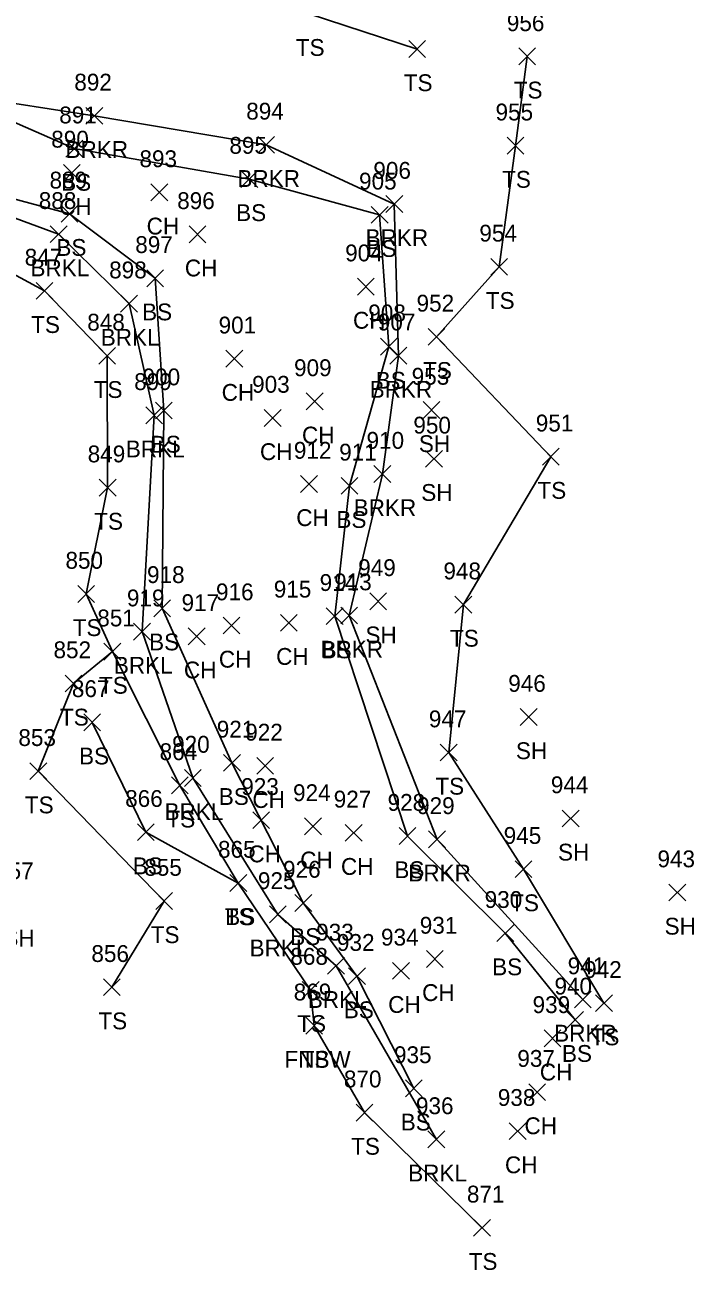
# Model space of a CAD drawing. Extents: x 1638705 to 1644019, y 630225 to 637423.
# Drawn here: x 1643939.5 to 1644019, y 636918.9 to 637066.8 of the extents above; entities that cross this region are included whole.
import ezdxf

# ---------------------------------------------------------------- set-up
doc = ezdxf.new("R2010")
doc.units = 0
for name, color, linetype in [('L_A', 7, 'Continuous'), ('L_I', 7, 'Continuous'), ('L_TIC', 7, 'Continuous'), ('LAWE', 7, 'Continuous'), ('LELB', 7, 'Continuous')]:
    doc.layers.add(name, color=color, linetype=linetype)

msp = doc.modelspace()

# ---------------------------------------------------------------- linework, layer by layer
at = {"layer": 'L_TIC'}
for points in [[(1643985.07, 637062.95), (1643987.07, 637064.95)], [(1643987.07, 637062.95), (1643985.07, 637064.95)], [(1643998.13, 637062.08), (1644000.13, 637064.08)], [(1644000.13, 637062.08), (1643998.13, 637064.08)], [(1643946.72, 637055.02), (1643948.72, 637057.02)], [(1643948.72, 637055.02), (1643946.72, 637057.02)], [(1643967.13, 637051.57), (1643969.13, 637053.57)], [(1643969.13, 637051.57), (1643967.13, 637053.57)], [(1643996.75, 637051.47), (1643998.75, 637053.47)], [(1643998.75, 637051.47), (1643996.75, 637053.47)], [(1643944.35, 637051.12), (1643946.35, 637053.12)], [(1643946.35, 637051.12), (1643944.35, 637053.12)], [(1643944.06, 637048.24), (1643946.06, 637050.24)], [(1643946.06, 637048.24), (1643944.06, 637050.24)], [(1643965.13, 637047.51), (1643967.13, 637049.51)], [(1643967.13, 637047.51), (1643965.13, 637049.51)], [(1643954.45, 637045.92), (1643956.45, 637047.92)], [(1643956.45, 637045.92), (1643954.45, 637047.92)], [(1643982.36, 637044.54), (1643984.36, 637046.54)], [(1643984.36, 637044.54), (1643982.36, 637046.54)], [(1643943.78, 637043.38), (1643945.78, 637045.38)], [(1643945.78, 637043.38), (1643943.78, 637045.38)], [(1643980.61, 637043.26), (1643982.61, 637045.26)], [(1643982.61, 637043.26), (1643980.61, 637045.26)], [(1643942.49, 637040.95), (1643944.49, 637042.95)], [(1643944.49, 637040.95), (1643942.49, 637042.95)], [(1643958.99, 637040.94), (1643960.99, 637042.94)], [(1643960.99, 637040.94), (1643958.99, 637042.94)], [(1643994.82, 637037.08), (1643996.82, 637039.08)], [(1643996.82, 637037.08), (1643994.82, 637039.08)], [(1643953.95, 637035.72), (1643955.95, 637037.72)], [(1643955.95, 637035.72), (1643953.95, 637037.72)], [(1643940.82, 637034.22), (1643942.82, 637036.22)], [(1643942.82, 637034.22), (1643940.82, 637036.22)], [(1643978.97, 637034.73), (1643980.97, 637036.73)], [(1643980.97, 637034.73), (1643978.97, 637036.73)], [(1643950.85, 637032.71), (1643952.85, 637034.71)], [(1643952.85, 637032.71), (1643950.85, 637034.71)], [(1643987.37, 637028.76), (1643989.37, 637030.76)], [(1643989.37, 637028.76), (1643987.37, 637030.76)], [(1643948.25, 637026.5), (1643950.25, 637028.5)], [(1643950.25, 637026.5), (1643948.25, 637028.5)], [(1643963.36, 637026.16), (1643965.36, 637028.16)], [(1643965.36, 637026.16), (1643963.36, 637028.16)], [(1643981.71, 637027.6), (1643983.71, 637029.6)], [(1643983.71, 637027.6), (1643981.71, 637029.6)], [(1643982.84, 637026.52), (1643984.84, 637028.52)], [(1643984.84, 637026.52), (1643982.84, 637028.52)], [(1643972.9, 637021.09), (1643974.9, 637023.09)], [(1643974.9, 637021.09), (1643972.9, 637023.09)], [(1643953.83, 637019.44), (1643955.83, 637021.44)], [(1643955.83, 637019.44), (1643953.83, 637021.44)], [(1643954.99, 637020), (1643956.99, 637022)], [(1643956.99, 637020), (1643954.99, 637022)], [(1643967.91, 637019.12), (1643969.91, 637021.12)], [(1643969.91, 637019.12), (1643967.91, 637021.12)], [(1643986.78, 637020.07), (1643988.78, 637022.07)], [(1643988.78, 637020.07), (1643986.78, 637022.07)], [(1644000.95, 637014.52), (1644002.95, 637016.52)], [(1644002.95, 637014.52), (1644000.95, 637016.52)], [(1643987.07, 637014.27), (1643989.07, 637016.27)], [(1643989.07, 637014.27), (1643987.07, 637016.27)], [(1643980.94, 637012.46), (1643982.94, 637014.46)], [(1643982.94, 637012.46), (1643980.94, 637014.46)], [(1643948.31, 637010.85), (1643950.31, 637012.85)], [(1643950.31, 637010.85), (1643948.31, 637012.85)], [(1643972.22, 637011.28), (1643974.22, 637013.28)], [(1643974.22, 637011.28), (1643972.22, 637013.28)], [(1643977.04, 637011.06), (1643979.04, 637013.06)], [(1643979.04, 637011.06), (1643977.04, 637013.06)], [(1643945.75, 636998.21), (1643947.75, 637000.21)], [(1643947.75, 636998.21), (1643945.75, 637000.21)], [(1643980.44, 636997.34), (1643982.44, 636999.34)], [(1643982.44, 636997.34), (1643980.44, 636999.34)], [(1643990.56, 636996.95), (1643992.56, 636998.95)], [(1643992.56, 636996.95), (1643990.56, 636998.95)], [(1643954.79, 636996.51), (1643956.79, 636998.51)], [(1643956.79, 636996.51), (1643954.79, 636998.51)], [(1643975.28, 636995.57), (1643977.28, 636997.57)], [(1643977.28, 636995.57), (1643975.28, 636997.57)], [(1643977, 636995.65), (1643979, 636997.65)], [(1643979, 636995.65), (1643977, 636997.65)], [(1643952.4, 636993.74), (1643954.4, 636995.74)], [(1643954.4, 636993.74), (1643952.4, 636995.74)], [(1643963.03, 636994.46), (1643965.03, 636996.46)], [(1643965.03, 636994.46), (1643963.03, 636996.46)], [(1643969.83, 636994.79), (1643971.83, 636996.79)], [(1643971.83, 636994.79), (1643969.83, 636996.79)], [(1643958.88, 636993.18), (1643960.88, 636995.18)], [(1643960.88, 636993.18), (1643958.88, 636995.18)], [(1643948.87, 636991.36), (1643950.87, 636993.36)], [(1643950.87, 636991.36), (1643948.87, 636993.36)], [(1643948.87, 636991.36), (1643950.87, 636993.36)], [(1643950.87, 636991.36), (1643948.87, 636993.36)], [(1643944.25, 636987.58), (1643946.25, 636989.58)], [(1643946.25, 636987.58), (1643944.25, 636989.58)], [(1643998.31, 636983.59), (1644000.31, 636985.59)], [(1644000.31, 636983.59), (1643998.31, 636985.59)], [(1643946.47, 636982.96), (1643948.47, 636984.96)], [(1643948.47, 636982.96), (1643946.47, 636984.96)], [(1643988.82, 636979.37), (1643990.82, 636981.37)], [(1643990.82, 636979.37), (1643988.82, 636981.37)], [(1643963.07, 636978.15), (1643965.07, 636980.15)], [(1643965.07, 636978.15), (1643963.07, 636980.15)], [(1643967.01, 636977.79), (1643969.01, 636979.79)], [(1643969.01, 636977.79), (1643967.01, 636979.79)], [(1643940.07, 636977.15), (1643942.07, 636979.15)], [(1643942.07, 636977.15), (1643940.07, 636979.15)], [(1643958.42, 636976.35), (1643960.42, 636978.35)], [(1643960.42, 636976.35), (1643958.42, 636978.35)], [(1643956.89, 636975.47), (1643958.89, 636977.47)], [(1643958.89, 636975.47), (1643956.89, 636977.47)], [(1644003.31, 636971.54), (1644005.31, 636973.54)], [(1644005.31, 636971.54), (1644003.31, 636973.54)], [(1643966.54, 636971.33), (1643968.54, 636973.33)], [(1643968.54, 636971.33), (1643966.54, 636973.33)], [(1643972.69, 636970.6), (1643974.69, 636972.6)], [(1643974.69, 636970.6), (1643972.69, 636972.6)], [(1643952.85, 636969.91), (1643954.85, 636971.91)], [(1643954.85, 636969.91), (1643952.85, 636971.91)], [(1643977.53, 636969.84), (1643979.53, 636971.84)], [(1643979.53, 636969.84), (1643977.53, 636971.84)], [(1643983.92, 636969.45), (1643985.92, 636971.45)], [(1643985.92, 636969.45), (1643983.92, 636971.45)], [(1643987.43, 636969.06), (1643989.43, 636971.06)], [(1643989.43, 636969.06), (1643987.43, 636971.06)], [(1643997.71, 636965.52), (1643999.71, 636967.52)], [(1643999.71, 636965.52), (1643997.71, 636967.52)], [(1643963.83, 636963.87), (1643965.83, 636965.87)], [(1643965.83, 636963.87), (1643963.83, 636965.87)], [(1643963.83, 636963.87), (1643965.83, 636965.87)], [(1643965.83, 636963.87), (1643963.83, 636965.87)], [(1644015.98, 636962.74), (1644017.98, 636964.74)], [(1644017.98, 636962.74), (1644015.98, 636964.74)], [(1643955.03, 636961.73), (1643957.03, 636963.73)], [(1643957.03, 636961.73), (1643955.03, 636963.73)], [(1643971.55, 636961.5), (1643973.55, 636963.5)], [(1643973.55, 636961.5), (1643971.55, 636963.5)], [(1643968.52, 636960.15), (1643970.52, 636962.15)], [(1643970.52, 636960.15), (1643968.52, 636962.15)], [(1643995.54, 636957.91), (1643997.54, 636959.91)], [(1643997.54, 636957.91), (1643995.54, 636959.91)], [(1643975.44, 636954.03), (1643977.44, 636956.03)], [(1643977.44, 636954.03), (1643975.44, 636956.03)], [(1643987.17, 636954.85), (1643989.17, 636956.85)], [(1643989.17, 636954.85), (1643987.17, 636956.85)], [(1643977.92, 636952.81), (1643979.92, 636954.81)], [(1643979.92, 636952.81), (1643977.92, 636954.81)], [(1643983.15, 636953.44), (1643985.15, 636955.44)], [(1643985.15, 636953.44), (1643983.15, 636955.44)], [(1643948.8, 636951.49), (1643950.8, 636953.49)], [(1643950.8, 636951.49), (1643948.8, 636953.49)], [(1643972.42, 636951.16), (1643974.42, 636953.16)], [(1643974.42, 636951.16), (1643972.42, 636953.16)], [(1644004.75, 636950.03), (1644006.75, 636952.03)], [(1644006.75, 636950.03), (1644004.75, 636952.03)], [(1644007.26, 636949.59), (1644009.26, 636951.59)], [(1644009.26, 636949.59), (1644007.26, 636951.59)], [(1643972.83, 636946.92), (1643974.83, 636948.92)], [(1643974.83, 636946.92), (1643972.83, 636948.92)], [(1643972.83, 636946.92), (1643974.83, 636948.92)], [(1643974.83, 636946.92), (1643972.83, 636948.92)], [(1644003.83, 636947.62), (1644005.83, 636949.62)], [(1644005.83, 636947.62), (1644003.83, 636949.62)], [(1644001.15, 636945.42), (1644003.15, 636947.42)], [(1644003.15, 636945.42), (1644001.15, 636947.42)], [(1643984.68, 636939.47), (1643986.68, 636941.47)], [(1643986.68, 636939.47), (1643984.68, 636941.47)], [(1643999.33, 636939.03), (1644001.33, 636941.03)], [(1644001.33, 636939.03), (1643999.33, 636941.03)], [(1643978.82, 636936.59), (1643980.82, 636938.59)], [(1643980.82, 636936.59), (1643978.82, 636938.59)], [(1643987.35, 636933.41), (1643989.35, 636935.41)], [(1643989.35, 636933.41), (1643987.35, 636935.41)], [(1643997.01, 636934.39), (1643999.01, 636936.39)], [(1643999.01, 636934.39), (1643997.01, 636936.39)], [(1643992.78, 636922.91), (1643994.78, 636924.91)], [(1643994.78, 636922.91), (1643992.78, 636924.91)]]:
    msp.add_lwpolyline(points, dxfattribs=at)
at = {"layer": 'LAWE'}
for points in [[(1643920.85, 637053.85), (1643924.81, 637055.54), (1643932.9, 637058.3), (1643947.72, 637056.02), (1643968.13, 637052.57), (1643983.36, 637045.54), (1643983.84, 637027.52), (1643981.94, 637013.46), (1643978, 636996.65), (1643988.43, 636970.06), (1644005.75, 636951.03)], [(1643919.29, 637049.79), (1643922.02, 637046.26), (1643932.4, 637046.02), (1643943.49, 637041.95), (1643951.85, 637033.71), (1643954.83, 637020.44), (1643953.4, 636994.74), (1643959.42, 636977.35), (1643969.52, 636961.15), (1643976.44, 636955.03), (1643988.35, 636934.41)]]:
    msp.add_lwpolyline(points, dxfattribs=at)
at = {"layer": 'LELB'}
for points in [[(1643913.32, 637074.89), (1643919.98, 637075.96), (1643928.62, 637076.78), (1643934.09, 637075.7), (1643944.5, 637076.33), (1643955.28, 637072.94), (1643973.25, 637068.14), (1643986.07, 637063.95)], [(1644008.26, 636950.59), (1643998.71, 636966.52), (1643989.82, 636980.37), (1643991.56, 636997.95), (1644001.95, 637015.52), (1643988.37, 637029.76), (1643995.82, 637038.08), (1643997.75, 637052.47), (1643999.13, 637063.08)], [(1643919.9, 637050.36), (1643921.47, 637053.52), (1643925.5, 637055.06), (1643935.65, 637056.38), (1643945.35, 637052.12), (1643966.13, 637048.51), (1643981.61, 637044.26), (1643982.71, 637028.6), (1643978.04, 637012.06), (1643976.28, 636996.57), (1643984.92, 636970.45), (1643996.54, 636958.91), (1644004.83, 636948.62)], [(1643919.9, 637050.36), (1643922.64, 637048.27), (1643928.54, 637048.75), (1643944.78, 637044.38), (1643954.95, 637036.72), (1643955.99, 637021), (1643955.79, 636997.51), (1643964.07, 636979.15), (1643972.55, 636962.5), (1643978.92, 636953.81), (1643985.68, 636940.47)], [(1643908.72, 636993.2), (1643912.06, 637008.12), (1643918.34, 637027.28), (1643925.98, 637038.19), (1643927.97, 637042.71), (1643941.82, 637035.22), (1643949.25, 637027.5), (1643949.31, 637011.85), (1643946.75, 636999.21), (1643949.87, 636992.36), (1643957.89, 636976.47), (1643964.83, 636964.87), (1643973.42, 636952.16), (1643973.83, 636947.92), (1643979.82, 636937.59), (1643993.78, 636923.91)], [(1643949.87, 636992.36), (1643945.25, 636988.58), (1643941.07, 636978.15), (1643956.03, 636962.73), (1643949.8, 636952.49)], [(1643964.83, 636964.87), (1643953.85, 636970.91), (1643947.47, 636983.96)]]:
    msp.add_lwpolyline(points, dxfattribs=at)

# ---------------------------------------------------------------- texts
at = {"layer": 'L_A'}
for s, p in [('TS', (1643971.66, 637063.14)), ('TS', (1643984.48, 637058.95)), ('TS', (1643997.54, 637058.08)), ('BRKR', (1643944.31, 637051.02)), ('BS', (1643943.79, 637047.12)), ('BRKR', (1643964.72, 637047.57)), ('TS', (1643996.16, 637047.47)), ('CH', (1643943.55, 637044.24)), ('BS', (1643964.57, 637043.51)), ('CH', (1643953.94, 637041.92)), ('BRKR', (1643979.95, 637040.54)), ('BS', (1643943.22, 637039.38)), ('BS', (1643980.05, 637039.26)), ('BRKL', (1643940.14, 637036.95)), ('CH', (1643958.48, 637036.94)), ('TS', (1643994.23, 637033.08)), ('BS', (1643953.4, 637031.72)), ('CH', (1643978.45, 637030.73)), ('TS', (1643940.23, 637030.22)), ('BRKL', (1643948.49, 637028.71)), ('TS', (1643986.78, 637024.76)), ('BS', (1643981.15, 637023.6)), ('TS', (1643947.66, 637022.5)), ('CH', (1643962.85, 637022.16)), ('BRKR', (1643980.43, 637022.52)), ('BS', (1643954.43, 637016)), ('CH', (1643972.39, 637017.09)), ('SH', (1643986.27, 637016.07)), ('BRKL', (1643951.47, 637015.44)), ('CH', (1643967.4, 637015.12)), ('SH', (1643986.56, 637010.27)), ('TS', (1644000.36, 637010.52)), ('BRKR', (1643978.53, 637008.46)), ('CH', (1643971.71, 637007.28)), ('BS', (1643976.48, 637007.06)), ('TS', (1643947.72, 637006.85)), ('TS', (1643945.16, 636994.21)), ('BS', (1643954.23, 636992.51)), ('SH', (1643979.93, 636993.34)), ('TS', (1643989.97, 636992.95)), ('CH', (1643969.32, 636990.79)), ('BRKR', (1643974.59, 636991.65)), ('BS', (1643974.72, 636991.57)), ('BRKL', (1643950.05, 636989.74)), ('CH', (1643958.37, 636989.18)), ('CH', (1643962.52, 636990.46)), ('TS', (1643948.28, 636987.36)), ('TS', (1643948.28, 636987.36)), ('TS', (1643943.65, 636983.58)), ('BS', (1643945.91, 636978.96)), ('SH', (1643997.8, 636979.59)), ('TS', (1643988.23, 636975.37)), ('TS', (1643939.48, 636973.15)), ('BS', (1643962.51, 636974.15)), ('CH', (1643966.5, 636973.79)), ('BRKL', (1643956.07, 636972.35)), ('TS', (1643956.3, 636971.47)), ('CH', (1643966.03, 636967.33)), ('SH', (1644002.8, 636967.54)), ('BS', (1643952.3, 636965.91)), ('CH', (1643972.18, 636966.6)), ('CH', (1643977.02, 636965.84)), ('BS', (1643983.36, 636965.45)), ('BRKR', (1643985.02, 636965.06)), ('TS', (1643997.12, 636961.52)), ('TS', (1643963.24, 636959.87)), ('BS', (1643963.27, 636959.87)), ('SH', (1644015.46, 636958.74)), ('SH', (1643936.92, 636957.32)), ('TS', (1643954.43, 636957.73)), ('BS', (1643970.99, 636957.5)), ('BRKL', (1643966.17, 636956.15)), ('BS', (1643994.98, 636953.91)), ('CH', (1643986.66, 636950.85)), ('BRKL', (1643973.08, 636950.03)), ('CH', (1643982.63, 636949.44)), ('BS', (1643977.36, 636948.81)), ('TS', (1643948.21, 636947.49)), ('TS', (1643971.83, 636947.16)), ('BRKR', (1644002.34, 636946.03)), ('TS', (1644006.67, 636945.59)), ('BS', (1644003.27, 636943.62)), ('FNBW', (1643970.3, 636942.92)), ('TS', (1643972.24, 636942.92)), ('CH', (1644000.64, 636941.42)), ('BS', (1643984.12, 636935.47)), ('CH', (1643998.82, 636935.03)), ('TS', (1643978.23, 636932.59)), ('CH', (1643996.5, 636930.39)), ('BRKL', (1643985, 636929.41)), ('TS', (1643992.19, 636918.91))]:
    msp.add_text(s, height=2, dxfattribs=at).set_placement(p)
at = {"layer": 'L_I'}
for s, p in [('956', (1643996.72, 637066.08)), ('892', (1643945.35, 637059.02)), ('891', (1643943.56, 637055.12)), ('894', (1643965.77, 637055.57)), ('955', (1643995.38, 637055.47)), ('890', (1643942.61, 637052.24)), ('895', (1643963.77, 637051.51)), ('893', (1643953.09, 637049.92)), ('906', (1643980.87, 637048.54)), ('889', (1643942.41, 637047.38)), ('905', (1643979.17, 637047.26)), ('888', (1643941.13, 637044.95)), ('896', (1643957.57, 637044.94)), ('954', (1643993.46, 637041.08)), ('897', (1643952.59, 637039.72)), ('847', (1643939.46, 637038.22)), ('904', (1643977.52, 637038.73)), ('898', (1643949.49, 637036.71)), ('952', (1643986, 637032.76)), ('908', (1643980.27, 637031.6)), ('848', (1643946.89, 637030.5)), ('901', (1643962.49, 637030.16)), ('907', (1643981.4, 637030.52)), ('909', (1643971.45, 637025.09)), ('899', (1643952.46, 637023.44)), ('900', (1643953.46, 637024)), ('953', (1643985.42, 637024.07)), ('903', (1643966.47, 637023.12)), ('950', (1643985.62, 637018.27)), ('951', (1644000.16, 637018.52)), ('910', (1643980.06, 637016.46)), ('849', (1643946.94, 637014.85)), ('912', (1643971.43, 637015.28)), ('911', (1643976.81, 637015.06)), ('850', (1643944.3, 637002.21)), ('949', (1643979.07, 637001.34)), ('918', (1643953.99, 637000.51)), ('914', (1643974.49, 636999.57)), ('913', (1643976.21, 636999.65)), ('948', (1643989.19, 637000.95)), ('916', (1643962.18, 636998.46)), ('915', (1643969.04, 636998.79)), ('919', (1643951.6, 636997.74)), ('917', (1643958.09, 636997.18)), ('851', (1643948.08, 636995.36)), ('851', (1643948.08, 636995.36)), ('852', (1643942.88, 636991.58)), ('867', (1643945.06, 636986.96)), ('946', (1643996.89, 636987.59)), ('947', (1643987.46, 636983.37)), ('921', (1643962.27, 636982.15)), ('922', (1643965.65, 636981.79)), ('853', (1643938.71, 636981.15)), ('920', (1643956.97, 636980.35)), ('864', (1643955.48, 636979.47)), ('923', (1643965.18, 636975.33)), ('924', (1643971.33, 636974.6)), ('944', (1644001.95, 636975.54)), ('866', (1643951.39, 636973.91)), ('927', (1643976.16, 636973.84)), ('928', (1643982.56, 636973.45)), ('929', (1643986.06, 636973.06)), ('945', (1643996.35, 636969.52)), ('865', (1643962.42, 636967.87)), ('865', (1643962.42, 636967.87)), ('855', (1643953.66, 636965.73)), ('926', (1643970.14, 636965.5)), ('943', (1644014.61, 636966.74)), ('857', (1643936.06, 636965.32)), ('925', (1643967.16, 636964.15)), ('930', (1643994.09, 636961.91)), ('931', (1643986.38, 636958.85)), ('933', (1643974.08, 636958.03)), ('932', (1643976.55, 636956.81)), ('934', (1643981.78, 636957.44)), ('856', (1643947.38, 636955.49)), ('868', (1643971.01, 636955.16)), ('941', (1644003.95, 636954.03)), ('942', (1644005.9, 636953.59)), ('869', (1643971.41, 636950.92)), ('869', (1643971.41, 636950.92)), ('940', (1644002.38, 636951.62)), ('939', (1643999.78, 636949.42)), ('935', (1643983.32, 636943.47)), ('937', (1643997.97, 636943.03)), ('870', (1643977.37, 636940.59)), ('936', (1643985.93, 636937.41)), ('938', (1643995.65, 636938.39)), ('871', (1643991.98, 636926.91))]:
    msp.add_text(s, height=2, dxfattribs=at).set_placement(p)

doc.saveas('drawing.dxf')
